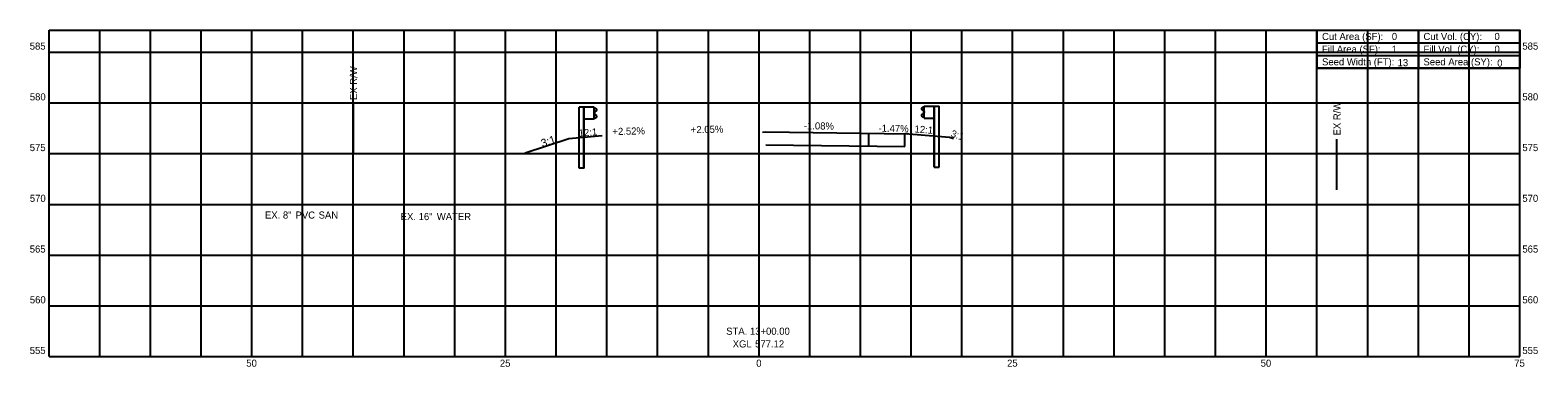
# Model space of a CAD drawing. Extents: x -72 to 77, y 554 to 587.
import ezdxf

# ---------------------------------------------------------------- set-up
doc = ezdxf.new("R2010")
doc.units = 0
for name, color, linetype in [('Default', 7, 'Continuous'), ('DR_X_Cells', 7, 'Continuous'), ('DR_X_GenericNode', 7, 'Continuous'), ('GK_Drainage_Nodes', 7, 'Continuous'), ('PF_X_Ground_Line', 7, 'Continuous'), ('RD_X_Cells', 7, 'Continuous'), ('SN_X_Public', 7, 'Continuous'), ('UT_X_Sanitary_Line', 7, 'Continuous'), ('UT_X_Telecom_Cells', 7, 'Continuous'), ('UT_X_Water', 7, 'Continuous'), ('VG_X_Cells', 7, 'Continuous')]:
    doc.layers.add(name, color=color, linetype=linetype)

msp = doc.modelspace()

# ---------------------------------------------------------------- linework, layer by layer
at = {"layer": 'Default'}
msp.add_circle((75, 587.17), 0.000417, dxfattribs=at)
msp.add_circle((75, 587.17), 0.000417, dxfattribs=at)
msp.add_circle((75, 587.17), 0.000417, dxfattribs=at)
msp.add_circle((75, 587.17), 0.000417, dxfattribs=at)
msp.add_circle((75, 587.17), 0.000417, dxfattribs=at)
msp.add_circle((75, 587.17), 0.000417, dxfattribs=at)
msp.add_circle((75, 587.17), 0.000417, dxfattribs=at)
msp.add_circle((75, 587.17), 0.000417, dxfattribs=at)
msp.add_circle((75, 587.17), 0.000417, dxfattribs=at)
msp.add_circle((75, 587.17), 0.000417, dxfattribs=at)
msp.add_circle((75, 587.17), 0.000417, dxfattribs=at)
msp.add_circle((75, 587.17), 0.000417, dxfattribs=at)
at = {"layer": 'DR_X_Cells'}
for p, q in [((0.34, 577.13), (0.67, 577.14)), ((0.67, 577.14), (14.66, 576.96)), ((10.79, 577), (10.79, 575.74)), ((14.66, 576.96), (14.38, 576.96)), ((14.38, 575.7), (14.38, 576.96)), ((0.67, 575.88), (14.38, 575.7))]:
    msp.add_line(p, q, dxfattribs=at)
at = {"layer": 'DR_X_GenericNode'}
for p, q in [((-70, 587.17), (75, 587.17)), ((-70, 555), (-70, 587.17)), ((-65, 555), (-65, 587.17)), ((-60, 555), (-60, 587.17)), ((-55, 555), (-55, 587.17)), ((-50, 555), (-50, 587.17)), ((-45, 555), (-45, 587.17)), ((-40, 555), (-40, 587.17)), ((-35, 555), (-35, 587.17)), ((-30, 555), (-30, 587.17)), ((-25, 555), (-25, 587.17)), ((-20, 555), (-20, 587.17)), ((-15, 555), (-15, 587.17)), ((-10, 555), (-10, 587.17)), ((-5, 555), (-5, 587.17)), ((0, 555), (0, 587.17)), ((5, 555), (5, 587.17)), ((10, 555), (10, 587.17)), ((15, 555), (15, 587.17)), ((20, 555), (20, 587.17)), ((25, 555), (25, 587.17)), ((30, 555), (30, 587.17)), ((35, 555), (35, 587.17)), ((40, 555), (40, 587.17)), ((45, 555), (45, 587.17)), ((50, 555), (50, 587.17)), ((55, 555), (55, 587.17)), ((60, 555), (60, 587.17)), ((65, 555), (65, 587.17)), ((70, 555), (70, 587.17)), ((75, 555), (75, 587.17)), ((-70, 585), (75, 585)), ((-70, 580), (75, 580)), ((-70, 575), (75, 575)), ((-70, 570), (75, 570)), ((-70, 565), (75, 565)), ((-70, 560), (75, 560)), ((-70, 555), (75, 555))]:
    msp.add_line(p, q, dxfattribs=at)
at = {"layer": 'GK_Drainage_Nodes'}
for p, q in [((-39.98, 574.93), (-39.98, 579.93)), ((56.97, 571.44), (56.97, 576.44))]:
    msp.add_line(p, q, dxfattribs=at)
at = {"layer": 'PF_X_Ground_Line'}
for p, q in [((16.29, 579.68), (17.29, 579.68)), ((16.29, 578.51), (16.29, 579.68)), ((17.26, 578.51), (17.26, 579.68)), ((17.28, 578.51), (17.28, 579.68)), ((17.29, 579.68), (17.76, 579.68)), ((17.29, 578.51), (17.29, 579.68)), ((17.75, 573.68), (17.75, 579.68)), ((17.76, 573.68), (17.76, 579.68)), ((-17.27, 579.58), (-17.75, 579.58)), ((-17.75, 573.58), (-17.75, 579.58)), ((-17.73, 573.58), (-17.73, 579.58)), ((-16.27, 579.58), (-17.27, 579.58)), ((-17.27, 578.41), (-17.27, 579.58)), ((-17.27, 578.41), (-17.27, 579.58)), ((-16.27, 578.41), (-17.27, 578.41)), ((-17.27, 573.58), (-17.27, 578.41)), ((-17.25, 578.41), (-17.25, 579.58)), ((-17.25, 573.58), (-17.25, 578.41)), ((-16.27, 578.41), (-16.27, 579.58)), ((-16.26, 579.5), (-16.26, 579.5)), ((-16.26, 579.5), (-16.17, 579.49)), ((-16.26, 579.49), (-16.26, 579.5)), ((-16.26, 579.49), (-16.26, 579.49)), ((-16.17, 579.48), (-16.26, 579.49)), ((-16.26, 579.04), (-16.26, 579.04)), ((-16.26, 578.95), (-16.26, 579.04)), ((-16.26, 578.96), (-16.26, 579.02)), ((-16.26, 578.95), (-16.26, 578.95)), ((-16.25, 579.04), (-16.25, 579.04)), ((-16.25, 579.04), (-16.25, 578.95)), ((-16.25, 578.96), (-16.25, 579.02)), ((-16.25, 578.95), (-16.25, 578.95)), ((-16.25, 578.49), (-16.17, 578.51)), ((-16.17, 578.5), (-16.25, 578.48)), ((-16.25, 578.49), (-16.25, 578.49)), ((-16.25, 578.48), (-16.25, 578.49)), ((-16.25, 578.48), (-16.25, 578.48)), ((-16.22, 579.11), (-16.03, 579.25)), ((-16.22, 579.11), (-16.22, 579.11)), ((-16.22, 578.88), (-16.22, 578.88)), ((-16.03, 578.74), (-16.22, 578.88)), ((-16.03, 579.24), (-16.21, 579.1)), ((-16.21, 579.1), (-16.21, 579.1)), ((-16.21, 578.88), (-16.21, 578.88)), ((-16.21, 578.88), (-16.03, 578.75)), ((-16.17, 579.49), (-16.17, 579.49)), ((-16.17, 579.49), (-16.03, 579.38)), ((-16.17, 579.48), (-16.17, 579.48)), ((-16.03, 579.37), (-16.17, 579.48)), ((-16.17, 578.51), (-16.03, 578.61)), ((-16.02, 578.6), (-16.17, 578.5)), ((-16.15, 579.47), (-16.15, 579.47)), ((-16.15, 579.46), (-16.15, 579.46)), ((-16.15, 579.16), (-16.15, 579.16)), ((-16.15, 579.15), (-16.15, 579.15)), ((-16.03, 579.38), (-16.03, 579.38)), ((-16.03, 579.37), (-16.03, 579.37)), ((-16.03, 579.25), (-16.03, 579.25)), ((-16.03, 579.24), (-16.03, 579.24)), ((-16.03, 578.75), (-16.03, 578.75)), ((-16.03, 578.74), (-16.03, 578.74)), ((-16.03, 578.61), (-16.03, 578.61)), ((-16.02, 578.6), (-16.02, 578.6)), ((-16, 579.31), (-16, 579.31)), ((-16, 578.67), (-16, 578.67)), ((-15.99, 579.31), (-15.99, 579.31)), ((-15.99, 578.67), (-15.99, 578.67)), ((16, 578.78), (16, 578.78)), ((16.01, 579.41), (16.01, 579.41)), ((16.01, 578.78), (16.01, 578.78)), ((16.02, 579.41), (16.02, 579.41)), ((16.18, 579.59), (16.04, 579.48)), ((16.04, 579.48), (16.04, 579.48)), ((16.04, 579.34), (16.04, 579.34)), ((16.04, 579.34), (16.23, 579.2)), ((16.23, 578.98), (16.04, 578.85)), ((16.04, 578.85), (16.04, 578.85)), ((16.04, 578.7), (16.04, 578.7)), ((16.04, 578.7), (16.18, 578.6)), ((16.05, 579.47), (16.19, 579.58)), ((16.05, 579.47), (16.05, 579.47)), ((16.05, 579.35), (16.05, 579.35)), ((16.23, 579.21), (16.05, 579.35)), ((16.05, 578.84), (16.23, 578.98)), ((16.05, 578.84), (16.05, 578.84)), ((16.05, 578.71), (16.05, 578.71)), ((16.19, 578.61), (16.05, 578.71)), ((16.16, 579.57), (16.16, 579.57)), ((16.16, 579.25), (16.16, 579.25)), ((16.17, 579.56), (16.17, 579.56)), ((16.17, 579.26), (16.17, 579.26)), ((16.27, 579.6), (16.18, 579.59)), ((16.18, 579.59), (16.18, 579.59)), ((16.18, 578.6), (16.27, 578.58)), ((16.19, 579.58), (16.27, 579.59)), ((16.19, 579.58), (16.19, 579.58)), ((16.27, 578.59), (16.19, 578.61)), ((16.23, 579.21), (16.23, 579.21)), ((16.23, 579.2), (16.23, 579.2)), ((16.23, 578.98), (16.23, 578.98)), ((16.23, 578.98), (16.23, 578.98)), ((16.26, 579.14), (16.26, 579.14)), ((16.26, 579.14), (16.26, 579.05)), ((16.26, 579.06), (16.26, 579.12)), ((16.26, 579.05), (16.26, 579.05)), ((16.27, 579.6), (16.27, 579.6)), ((16.27, 579.59), (16.27, 579.6)), ((16.27, 579.59), (16.27, 579.59)), ((16.27, 579.14), (16.27, 579.14)), ((16.27, 579.05), (16.27, 579.14)), ((16.27, 579.06), (16.27, 579.12)), ((16.27, 579.05), (16.27, 579.05)), ((16.27, 578.59), (16.27, 578.59)), ((16.27, 578.58), (16.27, 578.59)), ((16.27, 578.58), (16.27, 578.58)), ((16.29, 578.51), (17.29, 578.51)), ((17.26, 573.68), (17.26, 578.51)), ((17.28, 573.68), (17.28, 578.51)), ((-17.25, 573.58), (-17.75, 573.58)), ((17.26, 573.68), (17.76, 573.68))]:
    msp.add_line(p, q, dxfattribs=at)
for points in [[(-16.24, 579.05), (-16.24, 578.93), (-16.25, 578.93), (-16.25, 579.05)], [(-16.24, 579.02), (-16.24, 578.96), (-16.21, 578.96), (-16.21, 579.02)], [(16.25, 579.12), (16.25, 579.06), (16.23, 579.06), (16.23, 579.12)], [(16.25, 579.15), (16.25, 579.03), (16.26, 579.03), (16.26, 579.15)]]:
    msp.add_lwpolyline(points, close=True, dxfattribs=at)
for centre, radius, start, end in [((-16.17, 579.04), 0.0886, 126.318, 180.0944), ((-16.17, 578.95), 0.0886, 180.0944, 233.8707), ((-16.17, 579.04), 0.0788, 126.318, 180.0944), ((-16.17, 578.95), 0.0788, 180.0944, 233.8707), ((-16.08, 579.31), 0.0886, 306.318, 53.2212), ((-16.08, 579.31), 0.0787, 306.318, 53.2212), ((-16.08, 578.67), 0.0886, 306.9675, 53.8707), ((-16.08, 578.67), 0.0787, 306.9675, 53.8707), ((16.09, 578.78), 0.0886, 126.1293, 233.0325), ((16.09, 579.41), 0.0886, 126.7788, 233.682), ((16.09, 578.78), 0.0787, 126.1293, 233.0325), ((16.09, 579.41), 0.0787, 126.7788, 233.682), ((16.18, 579.14), 0.0886, 359.9056, 53.682), ((16.18, 579.14), 0.0788, 359.9056, 53.682), ((16.18, 579.05), 0.0886, 306.1293, 359.9056), ((16.18, 579.05), 0.0788, 306.1293, 359.9056)]:
    msp.add_arc(centre, radius, start, end, dxfattribs=at)
at = {"layer": 'SN_X_Public'}
for points in [[(-23.05, 575.07), (-18.75, 576.5), (-15.46, 576.78)], [(19.17, 576.46), (18.76, 576.6), (14.38, 576.96)]]:
    msp.add_lwpolyline(points, dxfattribs=at)
at = {"layer": 'UT_X_Telecom_Cells'}
msp.add_lwpolyline([(55, 587.17), (75, 587.17), (75, 583.42), (55, 583.42)], close=True, dxfattribs=at)
at = {"layer": 'UT_X_Water'}
for p, q in [((55, 587.17), (75, 587.17)), ((55, 587.17), (55, 584.67)), ((65, 587.17), (65, 583.42)), ((75, 587.17), (75, 584.67)), ((55, 585.92), (75, 585.92)), ((55, 584.67), (75, 584.67)), ((63.3, 584.05), (63.3, 584.05)), ((72.95, 584.05), (72.95, 584.05))]:
    msp.add_line(p, q, dxfattribs=at)
msp.add_lwpolyline([(55, 584.67), (55, 583.42), (75, 583.42), (75, 584.67)], dxfattribs=at)

# ---------------------------------------------------------------- texts
at = {"layer": 'GK_Drainage_Nodes'}
for p in [(-39.63, 580.28), (57.32, 576.79)]:
    msp.add_text('EX R/W', height=0.7, rotation=90, dxfattribs=at).set_placement(p)
at = {"layer": 'RD_X_Cells'}
for s, p in [('EX. 16"', (-35.33, 568.45)), ('WATER', (-31.77, 568.45))]:
    msp.add_text(s, height=0.7, dxfattribs=at).set_placement(p)
at = {"layer": 'UT_X_Sanitary_Line'}
for s, p in [('585', (-71.9, 585.25)), ('Cut Area (SF):', (55.5, 586.2)), ('Fill Area (SF):', (55.5, 584.95)), ('0', (62.38, 586.2)), ('1', (62.38, 584.95)), ('Cut Vol. (CY):', (65.5, 586.2)), ('Fill Vol. (CY):', (65.5, 584.95)), ('0', (72.5, 586.2)), ('0', (72.5, 584.95)), ('585', (75.25, 585.25)), ('Seed Width (FT):', (55.5, 583.7)), ('13', (62.95, 583.62)), ('Seed Area (SY):', (65.5, 583.7)), ('0', (72.77, 583.58)), ('580', (-71.89, 580.25)), ('580', (75.25, 580.25)), ('575', (-71.9, 575.25)), ('575', (75.25, 575.25)), ('570', (-71.89, 570.25)), ('570', (75.25, 570.25)), ('565', (-71.9, 565.25)), ('565', (75.25, 565.25)), ('560', (-71.89, 560.25)), ('560', (75.25, 560.25)), ('STA. 13+00.00', (-3.24, 557.15)), ('555', (-71.9, 555.25)), ('XGL ', (-2.6, 555.9)), ('577.12', (-0.39, 555.9)), ('555', (75.25, 555.25)), ('50', (-50.55, 554)), ('25', (-25.55, 554)), ('0', (-0.28, 554)), ('25', (24.45, 554)), ('50', (49.45, 554)), ('75', (74.45, 554))]:
    msp.add_text(s, height=0.7, dxfattribs=at).set_placement(p)
for s, height, rotation, p in [('3:1', 0.77, 18.4451, (-21.35, 575.63)), ('12:1', 0.7, 4.7699, (-17.75, 576.67)), ('+', 0.7, 1.4428, (-14.47, 576.83)), ('2.52%', 0.7, 1.4428, (-13.9, 576.84)), ('+', 0.7, 1.1721, (-6.74, 577.01)), ('2.05%', 0.7, 1.1721, (-6.17, 577.02)), ('-1.08%', 0.7, 359.3828, (4.41, 577.4)), ('-1.47%', 0.7, 359.1555, (11.77, 577.16)), ('12:1', 0.7, 355.2351, (15.31, 577.1)), ('3:1', 0.7, 341.559, (18.85, 576.69))]:
    msp.add_text(s, height=height, rotation=rotation, dxfattribs=at).set_placement(p)
at = {"layer": 'VG_X_Cells'}
for s, p in [('EX. 8"', (-48.71, 568.6)), ('PVC', (-45.7, 568.6)), ('SAN', (-43.42, 568.6))]:
    msp.add_text(s, height=0.7, dxfattribs=at).set_placement(p)

doc.saveas('drawing.dxf')
